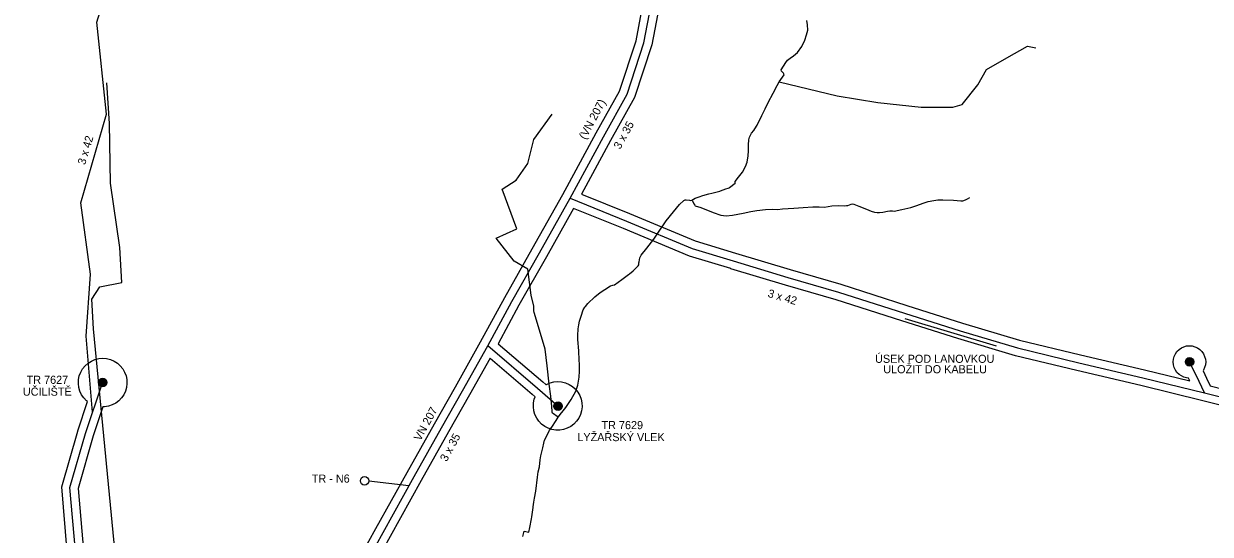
# Model space of a CAD drawing. Extents: x -439095 to -431527, y -1129525 to -1119219.
# Drawn here: x -438079 to -436616, y -1123382 to -1122754 of the extents above; entities that cross this region are included whole.
import ezdxf

# ---------------------------------------------------------------- set-up
doc = ezdxf.new("R2010")
doc.units = 0
for name, color, linetype in [('13861012_venkovní vedení elektrické sítě VN 1-35 kV_Stav', 7, 'Continuous'), ('14250012_plynovod STL_Stav', 7, 'Continuous'), ('14801013_OP vedení elektrické sítě_Stav', 7, 'Continuous'), ('Trafostanice', 7, 'Continuous'), ('Vrstva 13', 7, 'Continuous'), ('Vrstva 19', 7, 'Continuous'), ('Vrstva 21', 7, 'Continuous')]:
    doc.layers.add(name, color=color, linetype=linetype)

msp = doc.modelspace()

# ---------------------------------------------------------------- linework, layer by layer
at = {"layer": '13861012_venkovní vedení elektrické sítě VN 1-35 kV_Stav'}
msp.add_line((-437604.1, -1123323), (-437653.6, -1123317.3), dxfattribs=at)
for points in [[(-437994.2, -1123232.1), (-438002.3, -1123138.3), (-437996.7, -1123061.9), (-438008.7, -1122974.2), (-437977.1, -1122865), (-437977.1, -1122865.1), (-437989.1, -1122751.5), (-437967.6, -1122682.6), (-437917.7, -1122638.8), (-437924, -1122523.2), (-437915.1, -1122472.9)], [(-437670.6, -1123442.6), (-437636, -1123380.4), (-437597.6, -1123311.4), (-437564, -1123251.4), (-437538.1, -1123205.8), (-437506.9, -1123150.2), (-437477.3, -1123095.6), (-437443.3, -1123035.9), (-437405.4, -1122968.5), (-437364.4, -1122892.7), (-437335.2, -1122840.4), (-437314.3, -1122777), (-437305.5, -1122730.3)], [(-437405.4, -1122968.5), (-437335.8, -1122996.6), (-437254.7, -1123030.3), (-437204.4, -1123045.6), (-437204.4, -1123045.6), (-437136.7, -1123066.1), (-437074.5, -1123084.1), (-436993.2, -1123110), (-436924.2, -1123131.8), (-436853.7, -1123153), (-436778.2, -1123171.2), (-436699.3, -1123189.7), (-436622.9, -1123208.4), (-436534.9, -1123230.5)], [(-437506.8, -1123150), (-437445.7, -1123202.4), (-437420.6, -1123224.3)], [(-436623, -1123208.4), (-436629.6, -1123194.5), (-436641.4, -1123170)], [(-437977, -1123900.4), (-437982.6, -1123833.3), (-437982.6, -1123833.3), (-437987.7, -1123768.4), (-437994.8, -1123672.7), (-438001.8, -1123580), (-438008.5, -1123491), (-438015.4, -1123403.4), (-438022.1, -1123325), (-438003.1, -1123258.2), (-438003.1, -1123258.2), (-437981.9, -1123196)]]:
    msp.add_lwpolyline(points, dxfattribs=at)
at = {"layer": '14250012_plynovod STL_Stav'}
for points in [[(-437463.5, -1123385.1), (-437461.9, -1123378.8), (-437456.3, -1123379.9), (-437455.2, -1123374), (-437453.1, -1123363.5), (-437452.7, -1123361), (-437450.9, -1123349.5), (-437450.9, -1123348.8), (-437450.2, -1123342.9), (-437449.2, -1123338.1), (-437447.8, -1123329.5), (-437445.4, -1123312.2), (-437444.6, -1123305.4), (-437443.2, -1123299.5), (-437442.1, -1123290.8), (-437441.4, -1123285.7), (-437439, -1123275.9), (-437437.6, -1123270.4), (-437436.8, -1123266.5), (-437432.4, -1123257.8), (-437430.8, -1123254.2), (-437428.1, -1123250.4), (-437422.7, -1123242.3), (-437419.9, -1123238.4), (-437416, -1123233.1), (-437415.5, -1123232.5), (-437410.8, -1123226.2), (-437404.2, -1123216.3), (-437398.3, -1123206.2), (-437395.7, -1123198.9), (-437394.3, -1123188.9), (-437393.8, -1123181.7), (-437393.9, -1123174.3), (-437394.1, -1123166.8), (-437394.7, -1123157.7), (-437394.8, -1123157.1), (-437394.7, -1123156.8), (-437394.7, -1123156.4), (-437395.8, -1123142.6), (-437395.8, -1123142.3), (-437395.8, -1123142.3), (-437395.9, -1123142), (-437395.9, -1123141.9), (-437395.9, -1123141.7), (-437395.9, -1123137.8), (-437395.6, -1123129.6), (-437394.8, -1123124.3), (-437393.8, -1123119.8), (-437391.8, -1123113.7), (-437389.3, -1123106.1), (-437387.4, -1123102.9), (-437386.5, -1123101.7), (-437383.7, -1123098.2), (-437374.7, -1123089.9), (-437368.3, -1123084.7), (-437362.7, -1123080.8), (-437355.4, -1123076.4), (-437352.5, -1123075.5), (-437350.7, -1123075), (-437341.6, -1123068.8), (-437333.5, -1123062.6), (-437332.2, -1123061.6), (-437327.8, -1123057.8), (-437321.6, -1123051.8), (-437320.8, -1123050.5), (-437320.6, -1123048.7), (-437320.5, -1123048), (-437320.2, -1123046.7), (-437319.2, -1123042.1), (-437318.7, -1123040.3), (-437317.8, -1123038.5), (-437310.7, -1123030.2), (-437302.2, -1123018.9), (-437294.9, -1123007.8), (-437289.4, -1123000), (-437287.7, -1122997.7), (-437286.8, -1122996.4), (-437277.7, -1122985.2), (-437270.3, -1122976.4), (-437265, -1122971.3), (-437263.6, -1122970.5), (-437262.2, -1122970.5), (-437258.2, -1122971), (-437256.8, -1122971.3), (-437255.4, -1122970.9), (-437251, -1122968.3), (-437246.3, -1122966.8), (-437241.6, -1122965.2), (-437234.4, -1122963.2), (-437230.5, -1122962.1), (-437220.8, -1122959.8), (-437219.8, -1122959.3), (-437213.4, -1122956.8), (-437210.5, -1122955.9), (-437209.4, -1122955.7), (-437209.4, -1122955.7), (-437209.4, -1122955.7), (-437209.2, -1122955.6), (-437209.1, -1122955.6), (-437208.9, -1122955.4), (-437201.9, -1122949.8), (-437201.7, -1122949.7), (-437201.6, -1122949.6), (-437201.7, -1122949.4), (-437201.7, -1122949.3), (-437201.7, -1122949.3), (-437201.7, -1122949.3), (-437201.8, -1122948.9), (-437201.8, -1122947.8), (-437197.7, -1122942.5), (-437192.6, -1122936.3), (-437188.9, -1122929.3), (-437187.2, -1122924.1), (-437185.8, -1122916.4), (-437185.3, -1122910), (-437185.4, -1122902.7), (-437184.8, -1122896.6), (-437184.1, -1122893.3), (-437181.8, -1122888.5), (-437179, -1122884.9), (-437175.5, -1122879.7), (-437174.9, -1122878.4), (-437169, -1122866.5), (-437165, -1122858.5), (-437161, -1122850.6), (-437154.9, -1122838.9), (-437150.2, -1122829.7), (-437147.7, -1122824.9), (-437143.6, -1122819.2), (-437141.6, -1122816.6), (-437141.7, -1122815.4), (-437142.3, -1122814.4), (-437144.3, -1122812.5), (-437144.8, -1122811.8), (-437145.1, -1122810.3), (-437142.3, -1122805.9), (-437139.4, -1122801.3), (-437137.1, -1122798.3), (-437134.1, -1122796.1), (-437130, -1122793.2), (-437124.8, -1122788.9), (-437119.7, -1122781.4), (-437115.8, -1122773.7), (-437113.7, -1122767.3), (-437112.4, -1122761.5), (-437112.5, -1122755), (-437113.3, -1122749.7)], [(-437147.7, -1122824.9), (-437076, -1122842.3), (-437026.1, -1122850.6), (-436999.3, -1122853.4), (-436972.5, -1122856.2), (-436933.3, -1122856.2), (-436922, -1122853.1), (-436902.6, -1122828.8), (-436892.1, -1122809.7), (-436866.8, -1122795.4), (-436841.5, -1122781.1), (-436831, -1122783)], [(-437954.7, -1123524.9), (-437993.3, -1123129.4), (-437995.2, -1123092.7), (-437985.1, -1123077.6), (-437958.2, -1123072.2), (-437960.6, -1123029.4), (-437972, -1122949.8), (-437973.3, -1122876.6), (-437976.6, -1122826.2)], [(-437453.4, -1123087.8), (-437457.7, -1123056.1), (-437474.3, -1123046.2), (-437496.5, -1123017.8), (-437471.2, -1123006.1), (-437489.1, -1122957.4), (-437471.8, -1122946.3), (-437457.7, -1122925.9), (-437450.3, -1122896.3), (-437427.3, -1122865.1)], [(-437255.4, -1122970.9), (-437254.6, -1122971.9), (-437252.6, -1122975.3), (-437251.6, -1122977.2), (-437251.1, -1122977.8), (-437244.2, -1122979.8), (-437228.9, -1122986.2), (-437219.7, -1122989.2), (-437213, -1122990.1), (-437205.3, -1122989.4), (-437192.1, -1122986.7), (-437182.5, -1122984.9), (-437175, -1122983.5), (-437164.4, -1122982.3), (-437155.8, -1122982), (-437149.5, -1122982.4), (-437143.6, -1122981.6), (-437136.5, -1122981.2), (-437129.3, -1122980.6), (-437117.8, -1122979.8), (-437106.2, -1122979.2), (-437098.3, -1122979.2), (-437091.5, -1122979.4), (-437082.8, -1122978), (-437074.6, -1122977.5), (-437066.7, -1122977.7), (-437064.5, -1122977.6), (-437062.7, -1122977.3), (-437058.9, -1122975.9), (-437057.3, -1122975.6), (-437055.5, -1122975.9), (-437049.2, -1122978.1), (-437039.8, -1122982), (-437034.2, -1122984.3), (-437030.2, -1122985.5), (-437026.6, -1122985.9), (-437023.7, -1122986), (-437019.9, -1122985.5), (-437014, -1122984.5), (-437011.1, -1122984.1), (-437008, -1122984.1), (-437005.7, -1122984.5), (-436996.2, -1122982.4), (-436985.2, -1122979.8), (-436978.9, -1122977.9), (-436968.8, -1122974.3), (-436963.9, -1122972.7), (-436956.8, -1122971.2), (-436951.9, -1122970.4), (-436945.6, -1122970.3), (-436932.5, -1122970.9), (-436923.7, -1122971.6), (-436920.9, -1122971.6), (-436917.8, -1122970.4), (-436915.2, -1122969.2), (-436912.5, -1122967.4)], [(-437419.9, -1123238.4), (-437419.9, -1123238.4), (-437420.3, -1123238.1), (-437427.1, -1123233.3), (-437427.7, -1123232.6), (-437427.7, -1123232.2), (-437427.6, -1123231.5), (-437427.6, -1123231.4), (-437427.9, -1123225.2), (-437429.3, -1123212.3), (-437431, -1123197.5), (-437433.8, -1123175), (-437436.2, -1123154.6), (-437436.3, -1123154.4), (-437443.1, -1123131.1), (-437449.9, -1123109.2), (-437450.1, -1123107.4), (-437450.1, -1123101), (-437453.3, -1123088.4), (-437453.4, -1123087.8)]]:
    msp.add_lwpolyline(points, dxfattribs=at)
at = {"layer": '14801013_OP vedení elektrické sítě_Stav'}
for points in [[(-437283.2, -1122408.5), (-437281.3, -1122423.8), (-437273.5, -1122462.3), (-437264.9, -1122523.7), (-437254.8, -1122600.5), (-437283.5, -1122683.7), (-437295.7, -1122732.4), (-437304.6, -1122779.5), (-437326, -1122844.4), (-437355.6, -1122897.5), (-437391.3, -1122963.4)], [(-437943.7, -1123908), (-437926.8, -1123878.2), (-437926.8, -1123870.6), (-437922.5, -1123870.6), (-437903.2, -1123836.7), (-437867, -1123771.8), (-437831.4, -1123709.2), (-437793.9, -1123642.7), (-437752.5, -1123567.6), (-437730, -1123527.1), (-437679.3, -1123437.8), (-437644.8, -1123375.5), (-437606.3, -1123306.6), (-437572.7, -1123246.4), (-437546.8, -1123200.9), (-437515.7, -1123145.3), (-437486, -1123090.7), (-437452, -1123031), (-437414.2, -1122963.7), (-437373.1, -1122887.9), (-437344.4, -1122836.4), (-437324, -1122774.5), (-437315.3, -1122728.2)], [(-436616, -1123199.8), (-436532.6, -1123220.8), (-436445.5, -1123241.1), (-436379.7, -1123224), (-436309.9, -1123206.1), (-436242.7, -1123175.6), (-436176.4, -1123147.6), (-436105.4, -1123114.8), (-436041, -1123104.7), (-435970.4, -1123094.7), (-435914.8, -1123048.8), (-435854, -1122999.8), (-435852.2, -1122998.1), (-435807.7, -1122953.9), (-435793.4, -1122944.3)], [(-437391.3, -1122963.4), (-437332, -1122987.4), (-437251.3, -1123020.9), (-437201.6, -1123036), (-437133.9, -1123056.5), (-437071.6, -1123074.5), (-436990.2, -1123100.5), (-436921.3, -1123122.3), (-436851.1, -1123143.3), (-436775.9, -1123161.5), (-436696.9, -1123180), (-436641.1, -1123193.6)], [(-437401, -1122981.1), (-437434.6, -1123040.8), (-437468.5, -1123100.4), (-437494.2, -1123147.7)], [(-435841.1, -1123015.1), (-435902.2, -1123064.3), (-435962.1, -1123113.7), (-436038.1, -1123124.5), (-436099.5, -1123134.1), (-436168.3, -1123165.9), (-436234.7, -1123193.9), (-436303.2, -1123225), (-436374.7, -1123243.4), (-436445.2, -1123261.7), (-436537.3, -1123240.2), (-436625.3, -1123218.1), (-436701.6, -1123199.4), (-436780.5, -1123180.9), (-436856.3, -1123162.6), (-436927.2, -1123141.4), (-436996.2, -1123119.6), (-437077.4, -1123093.6), (-437139.6, -1123075.7), (-437207.2, -1123055.3), (-437207.2, -1123055.2), (-437258, -1123039.8), (-437339.6, -1123005.9), (-437401, -1122981.1)], [(-437494.2, -1123147.7), (-437439.1, -1123194.9), (-437435.3, -1123198.2)], [(-436642.8, -1123190.1), (-436645.1, -1123189.9), (-436648.5, -1123189), (-436651.6, -1123187.5), (-436654.5, -1123185.5), (-436657, -1123183.1), (-436659, -1123180.2), (-436660.4, -1123177.1), (-436661.3, -1123173.7), (-436661.6, -1123170.2), (-436661.3, -1123166.8), (-436660.4, -1123163.4), (-436659, -1123160.2), (-436657, -1123157.4), (-436654.5, -1123154.9), (-436651.6, -1123152.9), (-436648.5, -1123151.4), (-436645.1, -1123150.5)], [(-436645.1, -1123150.5), (-436641.6, -1123150.2), (-436638.2, -1123150.5), (-436634.8, -1123151.4), (-436631.6, -1123152.9), (-436628.8, -1123154.9), (-436626.3, -1123157.4), (-436624.3, -1123160.2), (-436622.9, -1123163.4), (-436621.9, -1123166.8), (-436621.6, -1123170.2), (-436621.9, -1123173.7), (-436622.9, -1123177.1), (-436624.3, -1123180.2), (-436624.9, -1123181.1)], [(-438000.3, -1123219.1), (-438001.7, -1123218.1), (-438005, -1123214.6), (-438007.8, -1123210.6), (-438009.8, -1123206.3), (-438011.2, -1123201.6), (-438011.7, -1123196.8), (-438011.6, -1123192), (-438010.6, -1123187.3), (-438008.9, -1123182.8), (-438006.5, -1123178.6), (-438003.4, -1123174.8), (-437999.8, -1123171.6), (-437995.7, -1123169.1), (-437991.3, -1123167.2), (-437986.6, -1123166), (-437981.8, -1123165.6), (-437977, -1123166), (-437972.3, -1123167.2), (-437967.8, -1123169.1), (-437963.7, -1123171.6), (-437960.1, -1123174.8), (-437957.1, -1123178.6), (-437954.7, -1123182.8), (-437953, -1123187.3), (-437952, -1123192), (-437951.8, -1123196.8), (-437952.4, -1123201.6), (-437953.7, -1123206.3), (-437955.8, -1123210.6), (-437958.5, -1123214.6), (-437961.9, -1123218.1), (-437965.7, -1123221), (-437970, -1123223.2), (-437974.6, -1123224.7), (-437979.4, -1123225.5), (-437981.4, -1123225.5)], [(-437504.1, -1123165.5), (-437529.4, -1123210.7), (-437555.3, -1123256.3), (-437588.9, -1123316.3), (-437627.3, -1123385.3), (-437661.9, -1123447.5), (-437710.8, -1123533.8)], [(-437504.1, -1123165.5), (-437452.2, -1123210), (-437448.4, -1123213.3)], [(-436624.9, -1123181.1), (-436620.6, -1123190.2), (-436616, -1123199.8)], [(-437435.3, -1123198.2), (-437434.6, -1123197.8), (-437430.1, -1123195.9), (-437425.5, -1123194.7), (-437420.6, -1123194.3), (-437415.8, -1123194.7), (-437411.1, -1123195.9), (-437406.7, -1123197.8), (-437402.6, -1123200.3), (-437399, -1123203.5), (-437396, -1123207.3), (-437393.5, -1123211.5), (-437391.8, -1123216), (-437390.9, -1123220.7), (-437390.7, -1123225.5), (-437391.2, -1123230.3), (-437392.6, -1123235), (-437394.7, -1123239.3), (-437397.4, -1123243.3), (-437400.7, -1123246.8), (-437404.6, -1123249.7), (-437408.9, -1123251.9), (-437413.5, -1123253.5), (-437418.2, -1123254.2), (-437423.1, -1123254.2), (-437427.8, -1123253.5), (-437432.4, -1123251.9), (-437436.7, -1123249.7), (-437440.5, -1123246.8), (-437443.9, -1123243.3), (-437446.6, -1123239.3), (-437448.7, -1123235), (-437450, -1123230.3), (-437450.6, -1123225.5), (-437450.4, -1123220.7), (-437449.5, -1123216), (-437448.4, -1123213.3)], [(-436641.1, -1123193.6), (-436642.8, -1123190.1)], [(-437988.1, -1123887.5), (-437992.6, -1123833.7), (-437992.6, -1123833.7), (-437997.7, -1123769.2), (-438004.7, -1123673.4), (-438011.8, -1123580.7), (-438018.5, -1123491.8), (-438025.4, -1123404.2), (-438032.2, -1123324), (-438012.6, -1123255.3), (-438012.5, -1123255), (-438000.3, -1123219.1)], [(-437981.4, -1123225.5), (-437993.5, -1123261.2), (-438012, -1123326), (-438005.4, -1123402.5), (-437998.5, -1123490.2), (-437991.8, -1123579.2), (-437984.8, -1123671.9), (-437977.8, -1123767.7), (-437972.7, -1123832.6), (-437967.1, -1123899.6)]]:
    msp.add_lwpolyline(points, dxfattribs=at)
at = {"layer": 'Trafostanice'}
for centre, radius in [((-436641.4, -1123170), 5.25), ((-436641.4, -1123170), 4.55), ((-436641.4, -1123170), 3.85), ((-436641.4, -1123170), 3.15), ((-436641.4, -1123170), 2.45), ((-436641.4, -1123170), 1.75), ((-436641.4, -1123170), 1.05), ((-436641.4, -1123170), 0.35), ((-437981.8, -1123195.6), 5.25), ((-437981.8, -1123195.6), 4.55), ((-437981.8, -1123195.6), 3.85), ((-437981.8, -1123195.6), 3.15), ((-437981.8, -1123195.6), 2.45), ((-437981.8, -1123195.6), 1.75), ((-437981.8, -1123195.6), 1.05), ((-437981.8, -1123195.6), 0.35), ((-437420.3, -1123224.7), 5.25), ((-437420.3, -1123224.7), 4.55), ((-437420.3, -1123224.7), 3.85), ((-437420.3, -1123224.7), 3.15), ((-437420.3, -1123224.7), 2.45), ((-437420.3, -1123224.7), 1.75), ((-437420.3, -1123224.7), 1.05), ((-437420.3, -1123224.7), 0.35)]:
    msp.add_circle(centre, radius, dxfattribs=at)
at = {"layer": 'Vrstva 13'}
msp.add_line((-436992.7, -1123116.7), (-436880, -1123150.2), dxfattribs=at)
at = {"layer": 'Vrstva 19'}
msp.add_circle((-437658.8, -1123316.7), 5.25, dxfattribs=at)

# ---------------------------------------------------------------- texts
at = {"layer": 'Vrstva 13'}
for s, rotation, p in [('(VN 207)', 61.6991, (-437386.3, -1122897)), ('3 x 35', 61.2474, (-437343.6, -1122909)), ('3 x 42', 73.2854, (-438003.5, -1122928.1)), ('3 x 42', 343.6959, (-437162.4, -1123089.9)), ('VN 207', 61.2472, (-437590, -1123268.4)), ('3 x 35', 61.2473, (-437557.7, -1123293.8))]:
    msp.add_text(s, height=10, rotation=rotation, dxfattribs=at).set_placement(p)
for s, p in [('ÚSEK POD LANOVKOU', (-437029.3, -1123171.3)), ('ULOŽIT DO KABELU', (-437019.2, -1123184.2)), ('TR 7627', (-438075.6, -1123197.2)), ('UČILIŠTĚ', (-438080.2, -1123211.8)), ('TR 7629', (-437366.7, -1123253)), ('LYŽAŘSKÝ VLEK', (-437396.5, -1123267.8))]:
    msp.add_text(s, height=10, dxfattribs=at).set_placement(p)
at = {"layer": 'Vrstva 21'}
msp.add_text('TR - N6', height=10, dxfattribs=at).set_placement((-437724, -1123318.9))

doc.saveas('drawing.dxf')
